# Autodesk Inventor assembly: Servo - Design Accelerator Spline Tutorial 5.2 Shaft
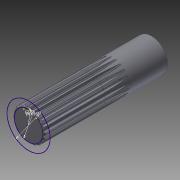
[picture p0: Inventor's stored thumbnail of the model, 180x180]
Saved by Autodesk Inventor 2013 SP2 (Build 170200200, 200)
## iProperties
Created: 2020-02
Part Number: Servo - Design Accelerator Spline Tutorial 5.2 Shaft
Document SubType Name: Assembly
Designer: DELL
Author: DELL
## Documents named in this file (3)
- C:\Users\DELL\Dropbox\Inventor\Projects\Quadcopter F450\Assemblies\Servo - Design Accelerator Spline Tutorial\Servo - Design Accelerator Spline Tutorial 5.2 Shaft.iam
- C:\Users\DELL\Dropbox\Inventor\Projects\Quadcopter F450\Assemblies\Servo - Design Accelerator Spline Tutorial\5.2mm Shaft - Spline Tutorial.ipt
- C:\Users\DELL\Dropbox\Inventor\Projects\Quadcopter F450\Assemblies\Servo - Design Accelerator Spline Tutorial\Servo - Design Accelerator Spline Tutorial 5.2 Shaft\Design Accelerator\Involute Spline Connection1.iam
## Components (2 placed, 2 different names)
1. Shaft Test 5.2:1
2. Involute Spline Connection:1 [sub-assembly]
